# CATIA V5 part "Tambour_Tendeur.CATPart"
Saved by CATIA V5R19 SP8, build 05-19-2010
Part number: Tambour_Tendeur
Nomenclature: 40
Material "Acier": density 7860 kg/m3, Young's modulus 2e+11 Pa, Poisson ratio 0.266, thermal expansion 1.17e-05 1/K
Bounding box of the stored display mesh (mm): x -235 to 235, y -20.985 to 20.985, z -20.985 to 20.985
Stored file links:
  C:\Users\rphgr\Desktop\0_Tapis_TC520B_vitesse\Tambour_Tendeur.CATPart
  D:\Programmes\DassaultSysteme\win_b64\startup\materials\French\Catalog.CATMaterial
  D:\Documents\1_Travail\1 - ac-limoges.fr\ac-limoges.fr\Emmanuel Maynard - STI2D_Turgot\3 - Supports\Tapis de course TC520B\Tapis de course TC520B_Ca\Poulie_inertie.CATPart
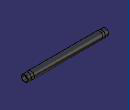
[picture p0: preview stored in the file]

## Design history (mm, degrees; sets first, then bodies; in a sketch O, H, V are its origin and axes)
AxisSystem1: origin (0, 0, 0), X (1, 0, 0), Y (0, 1, 0), Z (0, 0, 1)
Body1 (main body), material "Acier"
  Sketch1 on ZX plane of AxisSystem1, origin (0, 0, 0), H (0, 0, 1), V (1, 0, 0)
    axis line L1 (0, -410) -> (0, 345.5398)
    point P1 (0, -410)
    point P3 (21, 0)
    line L2 (21, 0) -> (21, -200)
    point P4 (21, -200)
    line L3 (21, -200) -> (19.5, -215)
    line L4 (19.5, -215) -> (19.5, -235)
    point P6 (19.5, -235)
    distance L4 L1 = 19.5
    distance L2 L1 = 21
    distance P6 H = 235
    length L4 = 20
    distance P4 P6 V = 35
    coincidence: P1 V, L3 P1, P3 H
    vertical: L1 V, L2 V, L4 V
  Shaft1: profile Sketch1, axis Sketch1.L1, angle 360, thin wall 0, second thickness 2
  Mirror1: of the body so far, about face of Shaft1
